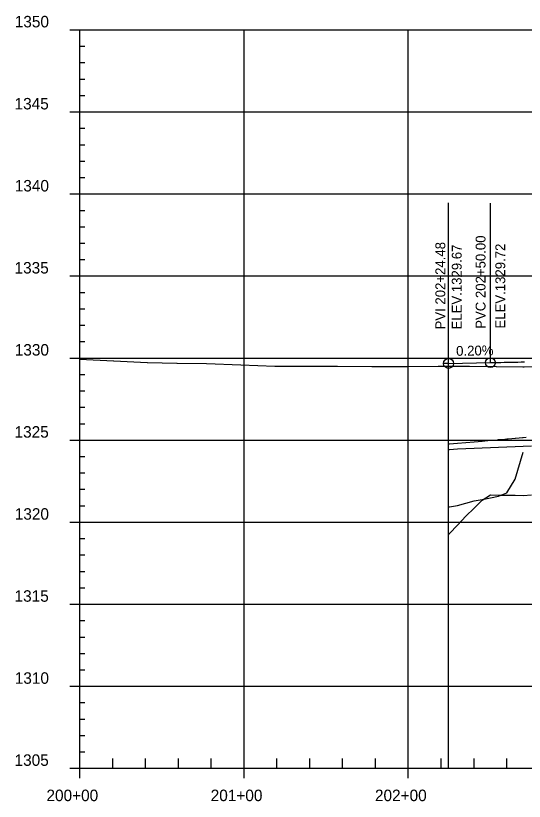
# Model space of a CAD drawing. Extents: x 1371206 to 1374178, y 379328 to 381511.
# Drawn here: x 1371205.6 to 1371515.2, y 379328.3 to 379807 of the extents above; entities that cross this region are included whole.
import ezdxf

# ---------------------------------------------------------------- set-up
doc = ezdxf.new("R2010")
doc.units = 0
for name, color, linetype in [('30', 7, 'Continuous'), ('37', 7, 'Continuous'), ('BRIDGE', 7, 'Continuous'), ('Default', 7, 'Continuous'), ('R_Exist Surface', 7, 'Continuous'), ('R_Profile Work Left', 7, 'Continuous'), ('R_Profile Work Right', 7, 'Continuous'), ('R_Vert Alg', 7, 'Continuous'), ('R_Vert Alg Annot', 7, 'Continuous')]:
    doc.layers.add(name, color=color, linetype=linetype)

msp = doc.modelspace()

# ---------------------------------------------------------------- linework, layer by layer
at = {"layer": '37'}
for p, q in [((1371238.63, 379798.35), (1371244.63, 379798.35)), ((1371238.63, 379798.35), (1371244.63, 379798.35)), ((1371244.63, 379348.35), (1371244.63, 379798.35)), ((1371244.63, 379798.35), (1374144.63, 379798.35)), ((1371244.63, 379798.35), (1374144.63, 379798.35)), ((1371344.63, 379348.35), (1371344.63, 379798.35)), ((1371444.63, 379348.35), (1371444.63, 379798.35)), ((1371244.63, 379788.35), (1371247.63, 379788.35)), ((1371244.63, 379778.35), (1371247.63, 379778.35)), ((1371244.63, 379768.35), (1371247.63, 379768.35)), ((1371244.63, 379758.35), (1371247.63, 379758.35)), ((1371238.63, 379748.35), (1371244.63, 379748.35)), ((1371244.63, 379748.35), (1374144.63, 379748.35)), ((1371244.63, 379738.35), (1371247.63, 379738.35)), ((1371244.63, 379728.35), (1371247.63, 379728.35)), ((1371244.63, 379718.35), (1371247.63, 379718.35)), ((1371244.63, 379708.35), (1371247.63, 379708.35)), ((1371238.63, 379698.35), (1371244.63, 379698.35)), ((1371244.63, 379698.35), (1374144.63, 379698.35)), ((1371244.63, 379688.35), (1371247.63, 379688.35)), ((1371244.63, 379678.35), (1371247.63, 379678.35)), ((1371244.63, 379668.35), (1371247.63, 379668.35)), ((1371244.63, 379658.35), (1371247.63, 379658.35)), ((1371238.63, 379648.35), (1371244.63, 379648.35)), ((1371244.63, 379648.35), (1374144.63, 379648.35)), ((1371244.63, 379638.35), (1371247.63, 379638.35)), ((1371244.63, 379628.35), (1371247.63, 379628.35)), ((1371244.63, 379618.35), (1371247.63, 379618.35)), ((1371244.63, 379608.35), (1371247.63, 379608.35)), ((1371238.63, 379598.35), (1371244.63, 379598.35)), ((1371244.63, 379598.35), (1372944.63, 379598.35)), ((1371244.63, 379598.35), (1374144.63, 379598.35)), ((1371244.63, 379588.35), (1371247.63, 379588.35)), ((1371244.63, 379578.35), (1371247.63, 379578.35)), ((1371244.63, 379568.35), (1371247.63, 379568.35)), ((1371244.63, 379558.35), (1371247.63, 379558.35)), ((1371238.63, 379548.35), (1371244.63, 379548.35)), ((1371244.63, 379548.35), (1374144.63, 379548.35)), ((1371244.63, 379538.35), (1371247.63, 379538.35)), ((1371244.63, 379528.35), (1371247.63, 379528.35)), ((1371244.63, 379518.35), (1371247.63, 379518.35)), ((1371244.63, 379508.35), (1371247.63, 379508.35)), ((1371238.63, 379498.35), (1371244.63, 379498.35)), ((1371244.63, 379498.35), (1374144.63, 379498.35)), ((1371244.63, 379488.35), (1371247.63, 379488.35)), ((1371244.63, 379478.35), (1371247.63, 379478.35)), ((1371244.63, 379468.35), (1371247.63, 379468.35)), ((1371244.63, 379458.35), (1371247.63, 379458.35)), ((1371238.63, 379448.35), (1371244.63, 379448.35)), ((1371244.63, 379448.35), (1374144.63, 379448.35)), ((1371244.63, 379438.35), (1371247.63, 379438.35)), ((1371244.63, 379428.35), (1371247.63, 379428.35)), ((1371244.63, 379418.35), (1371247.63, 379418.35)), ((1371244.63, 379408.35), (1371247.63, 379408.35)), ((1371238.63, 379398.35), (1371244.63, 379398.35)), ((1371244.63, 379398.35), (1374144.63, 379398.35)), ((1371244.63, 379388.35), (1371247.63, 379388.35)), ((1371244.63, 379378.35), (1371247.63, 379378.35)), ((1371244.63, 379368.35), (1371247.63, 379368.35)), ((1371244.63, 379358.35), (1371247.63, 379358.35)), ((1371264.63, 379348.35), (1371264.63, 379354.35)), ((1371284.63, 379348.35), (1371284.63, 379354.35)), ((1371304.63, 379348.35), (1371304.63, 379354.35)), ((1371324.63, 379348.35), (1371324.63, 379354.35)), ((1371364.63, 379348.35), (1371364.63, 379354.35)), ((1371384.63, 379348.35), (1371384.63, 379354.35)), ((1371404.63, 379348.35), (1371404.63, 379354.35)), ((1371424.63, 379348.35), (1371424.63, 379354.35)), ((1371464.63, 379348.35), (1371464.63, 379354.35)), ((1371484.63, 379348.35), (1371484.63, 379354.35)), ((1371504.63, 379348.35), (1371504.63, 379354.35)), ((1371238.63, 379348.35), (1371244.63, 379348.35)), ((1371244.63, 379348.35), (1374144.63, 379348.35)), ((1371244.63, 379342.35), (1371244.63, 379348.35)), ((1371344.63, 379342.35), (1371344.63, 379348.35)), ((1371444.63, 379342.35), (1371444.63, 379348.35))]:
    msp.add_line(p, q, dxfattribs=at)
at = {"layer": 'BRIDGE'}
msp.add_line((1371469.11, 379593.3), (1371469.11, 379593.53), dxfattribs=at)
msp.add_lwpolyline([(1371469.11, 379593.4), (1371469.11, 379595.07), (1371466.24, 379595.07)], dxfattribs=at)
at = {"layer": 'Default'}
for p, q in [((1371244.63, 379598.35), (1371244.63, 379597.7)), ((1371469.11, 379348.35), (1371469.11, 379593.3)), ((1371444.63, 379348.35), (1371469.11, 379348.35))]:
    msp.add_line(p, q, dxfattribs=at)
at = {"layer": 'R_Exist Surface'}
msp.add_lwpolyline([(1371244.63, 379597.7), (1371265.16, 379596.65), (1371265.27, 379596.65), (1371285.69, 379595.61), (1371285.88, 379595.59), (1371303.68, 379595.31), (1371303.82, 379595.3), (1371321.66, 379595.02), (1371321.77, 379595.02), (1371342.61, 379594.23), (1371363.28, 379593.44), (1371363.57, 379593.43), (1371382.05, 379593.38), (1371382.35, 379593.37), (1371382.66, 379593.36), (1371401.14, 379593.31), (1371401.57, 379593.32), (1371422.38, 379593.26), (1371422.77, 379593.27), (1371443.62, 379593.21), (1371443.92, 379593.21), (1371462.77, 379593.35), (1371462.89, 379593.36), (1371474.97, 379593.44), (1371481.86, 379593.49), (1371481.93, 379593.49), (1371498.15, 379593.21), (1371498.35, 379593.2), (1371514.43, 379592.93), (1371514.76, 379592.92), (1371515.07, 379592.93), (1371530.08, 379593.4)], dxfattribs=at)
at = {"layer": 'R_Profile Work Left'}
for points in [[(1371469.11, 379546.07), (1371469.63, 379546.11), (1371474.63, 379546.53), (1371479.63, 379546.95), (1371484.63, 379547.37), (1371489.63, 379547.79), (1371494.63, 379548.21), (1371496.8, 379548.39), (1371498.98, 379548.57), (1371499.63, 379548.63), (1371501.15, 379548.76), (1371503.33, 379548.94), (1371504.63, 379549.05), (1371505.5, 379549.13), (1371507.67, 379549.32), (1371509.63, 379549.49), (1371509.85, 379549.51), (1371512.02, 379549.7), (1371514.2, 379549.89), (1371514.63, 379549.92), (1371516.37, 379550.08)], [(1371469.11, 379491), (1371469.63, 379491.52), (1371474.63, 379496.57), (1371479.63, 379501.93), (1371484.63, 379506.86), (1371489.63, 379511.79), (1371494.63, 379514.91), (1371499.63, 379514.74), (1371504.63, 379514.75), (1371509.63, 379514.81), (1371514.63, 379514.65), (1371519.63, 379514.97)]]:
    msp.add_lwpolyline(points, dxfattribs=at)
at = {"layer": 'R_Profile Work Right'}
for points in [[(1371469.11, 379542.7), (1371469.63, 379542.72), (1371474.63, 379542.94), (1371479.63, 379543.15), (1371484.63, 379543.36), (1371489.63, 379543.57), (1371494.63, 379543.78), (1371499.63, 379544), (1371504.63, 379544.21), (1371509.63, 379544.42), (1371514.63, 379544.63), (1371519.63, 379544.85)], [(1371469.11, 379507.58), (1371469.63, 379507.66), (1371474.63, 379508.42), (1371479.63, 379509.96), (1371484.63, 379511.32), (1371489.63, 379512.21), (1371494.63, 379513.1), (1371499.63, 379514.17), (1371504.63, 379516.31), (1371509.63, 379524.53), (1371514.63, 379540.99)]]:
    msp.add_lwpolyline(points, dxfattribs=at)
at = {"layer": 'R_Vert Alg'}
msp.add_line((1371469.11, 379595.07), (1371494.63, 379595.57), dxfattribs=at)
msp.add_lwpolyline([(1371494.63, 379595.57), (1371496.71, 379595.61), (1371498.8, 379595.65), (1371500.88, 379595.7), (1371502.96, 379595.74), (1371505.05, 379595.79), (1371507.13, 379595.83), (1371509.21, 379595.88), (1371511.3, 379595.93), (1371513.38, 379595.98), (1371515.46, 379596.03)], dxfattribs=at)
for centre in [(1371469.11, 379595.07), (1371494.63, 379595.57)]:
    msp.add_circle(centre, 3, dxfattribs=at)
at = {"layer": 'R_Vert Alg Annot'}
for p, q in [((1371469.11, 379595.07), (1371469.11, 379692.92)), ((1371494.63, 379595.57), (1371494.63, 379692.8))]:
    msp.add_line(p, q, dxfattribs=at)

# ---------------------------------------------------------------- texts
at = {"layer": '30'}
for s, p in [('1350', (1371205.02, 379799.85)), ('1350', (1371205.02, 379799.85)), ('1345', (1371204.89, 379749.85)), ('1340', (1371205.02, 379699.85)), ('1335', (1371204.89, 379649.85)), ('1330', (1371205.02, 379599.85)), ('1325', (1371204.89, 379549.85)), ('1320', (1371205.02, 379499.85)), ('1315', (1371204.89, 379449.85)), ('1310', (1371205.02, 379399.85)), ('1305', (1371204.89, 379349.85)), ('200+00', (1371224.32, 379328.35)), ('201+00', (1371324.32, 379328.35)), ('202+00', (1371424.32, 379328.35))]:
    msp.add_text(s, height=7, dxfattribs=at).set_placement(p)
at = {"layer": 'R_Vert Alg Annot'}
for s, rotation, p in [('PVC 202+50.00', 90, (1371491.63, 379616.17)), ('PVI 202+24.48', 90, (1371467.11, 379615.76)), ('ELEV.1329.67', 90, (1371477.11, 379615.76)), ('ELEV.1329.72', 90, (1371503.63, 379616.32)), ('0.20%', 1.123, (1371473.79, 379599.67))]:
    msp.add_text(s, height=6, rotation=rotation, dxfattribs=at).set_placement(p)

doc.saveas('drawing.dxf')
